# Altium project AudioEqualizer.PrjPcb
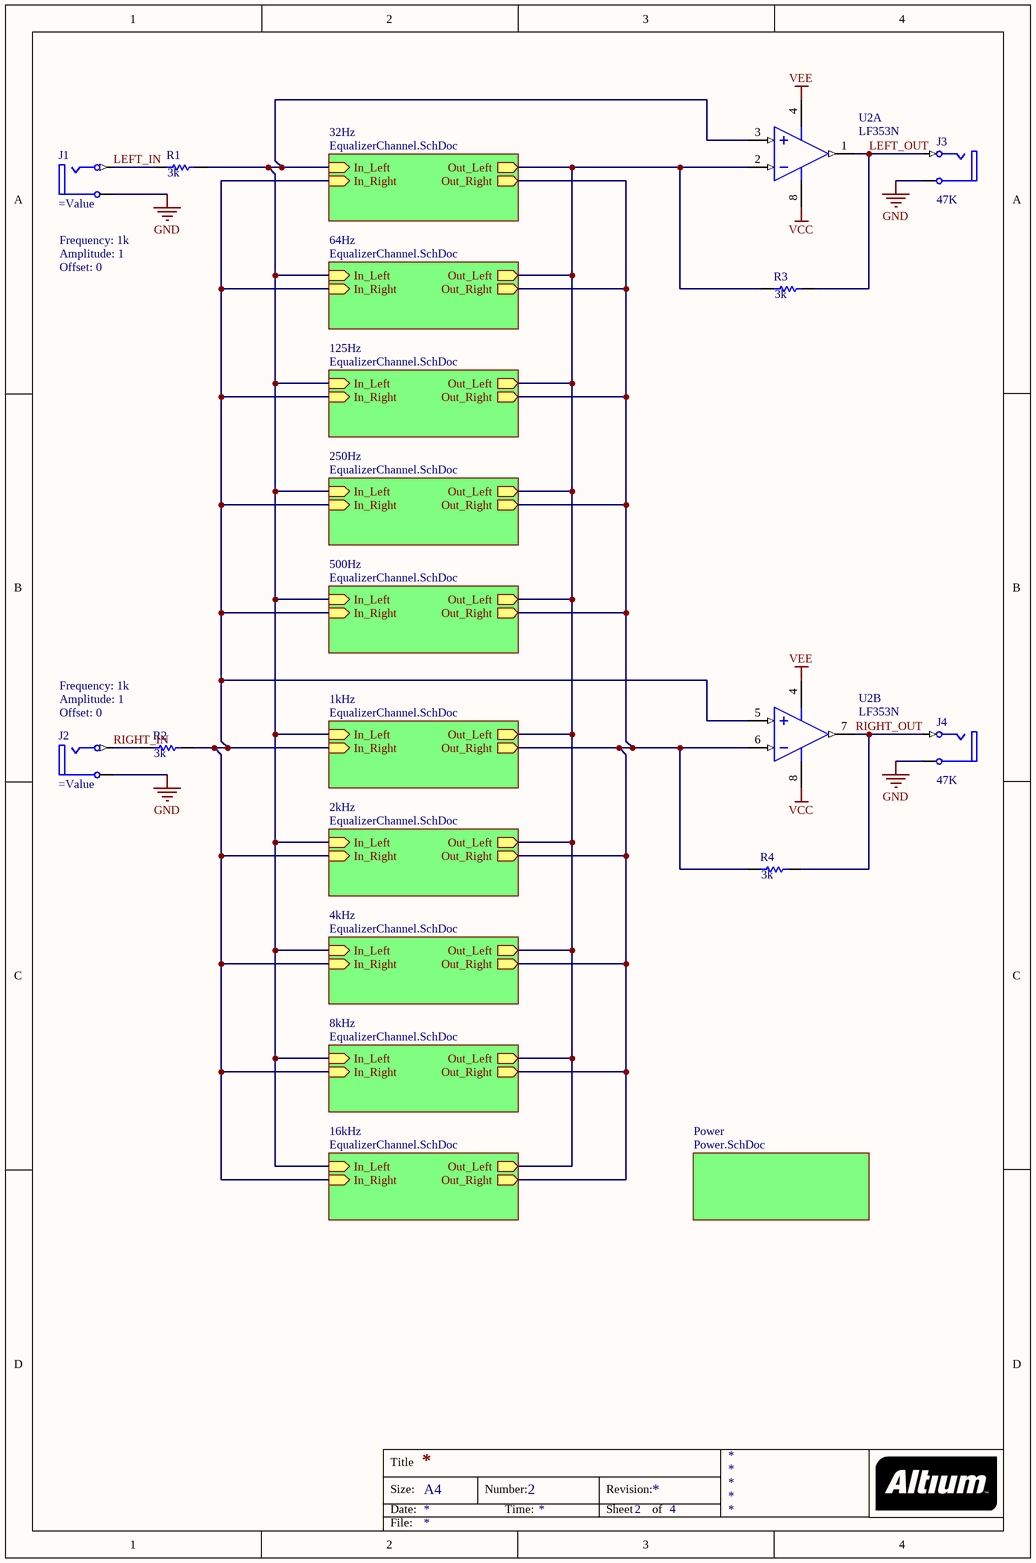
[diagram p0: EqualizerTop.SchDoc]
4 sheets, 139 parts. Net scope: hierarchical (ports join the sheet entries above them; power ports are global).
Sheets:
  EqualizerTop.SchDoc
    32Hz = EqualizerChannel.SchDoc
      Left = RCNetwork.SchDoc
      Right = RCNetwork.SchDoc
    64Hz = EqualizerChannel.SchDoc
      Left = RCNetwork.SchDoc
      Right = RCNetwork.SchDoc
    125Hz = EqualizerChannel.SchDoc
      Left = RCNetwork.SchDoc
      Right = RCNetwork.SchDoc
    250Hz = EqualizerChannel.SchDoc
      Left = RCNetwork.SchDoc
      Right = RCNetwork.SchDoc
    500Hz = EqualizerChannel.SchDoc
      Left = RCNetwork.SchDoc
      Right = RCNetwork.SchDoc
    1kHz = EqualizerChannel.SchDoc
      Left = RCNetwork.SchDoc
      Right = RCNetwork.SchDoc
    2kHz = EqualizerChannel.SchDoc
      Left = RCNetwork.SchDoc
      Right = RCNetwork.SchDoc
    4kHz = EqualizerChannel.SchDoc
      Left = RCNetwork.SchDoc
      Right = RCNetwork.SchDoc
    8kHz = EqualizerChannel.SchDoc
      Left = RCNetwork.SchDoc
      Right = RCNetwork.SchDoc
    16kHz = EqualizerChannel.SchDoc
      Left = RCNetwork.SchDoc
      Right = RCNetwork.SchDoc
    Power = Power.SchDoc

## Sheet EqualizerTop.SchDoc
size A4 portrait; DocumentNumber: 2; SheetNumber: 2; SheetTotal: 4

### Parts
J1  Offset: 0  Amplitude: 1  Frequency: 1k  [RCA/4.5-H2]
J2  Offset: 0  Amplitude: 1  Frequency: 1k  [RCA/4.5-H2]
J3  47K  [RCA/4.5-H2]
J4  47K  [RCA/4.5-H2]
R1  3k  [3216[1206]]
R2  3k  [3216[1206]]
R3  3k  [3216[1206]]
R4  3k  [3216[1206]]
U2  LF353N  [N08E]  (parts A,B of 2)

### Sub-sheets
1kHz = EqualizerChannel.SchDoc: In_Left (in), Out_Left (out), In_Right (in), Out_Right (out)  | C1_Value: 3.9nF; C2_Value: 0.22uF; R1_Value: 68k; R2_Value: 470; POT_SET: {SLIDER_1K}
2kHz = EqualizerChannel.SchDoc: In_Left (in), Out_Left (out), In_Right (in), Out_Right (out)  | C1_Value: 2nF; C2_Value: 0.1uF; R1_Value: 68k; R2_Value: 470; POT_SET: {SLIDER_2K}
4kHz = EqualizerChannel.SchDoc: In_Left (in), Out_Left (out), In_Right (in), Out_Right (out)  | C1_Value: 1.1nF; C2_Value: 0.056uF; R1_Value: 62k; R2_Value: 470; POT_SET: {SLIDER_4K}
8kHz = EqualizerChannel.SchDoc: In_Left (in), Out_Left (out), In_Right (in), Out_Right (out)  | C1_Value: 510pF; C2_Value: 0.022uF; R1_Value: 68k; R2_Value: 510; POT_SET: {SLIDER_8K}
16kHz = EqualizerChannel.SchDoc: In_Left (in), Out_Left (out), In_Right (in), Out_Right (out)  | C1_Value: 330pF; C2_Value: 0.012uF; R1_Value: 51k; R2_Value: 510; POT_SET: {SLIDER_16K}
32Hz = EqualizerChannel.SchDoc: In_Left (in), Out_Left (out), In_Right (in), Out_Right (out)  | C1_Value: 0.12uF; C2_Value: 4.7uF; R1_Value: 75k; R2_Value: 500; POT_SET: {SLIDER_32}
64Hz = EqualizerChannel.SchDoc: In_Left (in), Out_Left (out), In_Right (in), Out_Right (out)  | C1_Value: 0.056uF; C2_Value: 3.3uF; R1_Value: 68k; R2_Value: 510; POT_SET: {SLIDER_64}
125Hz = EqualizerChannel.SchDoc: In_Left (in), Out_Left (out), In_Right (in), Out_Right (out)  | C1_Value: 0.033uF; C2_Value: 1.5uF; R1_Value: 62k; R2_Value: 510; POT_SET: {SLIDER_125}
250Hz = EqualizerChannel.SchDoc: In_Left (in), Out_Left (out), In_Right (in), Out_Right (out)  | C1_Value: 0.015uF; C2_Value: 0.82uF; R1_Value: 68k; R2_Value: 470; POT_SET: {SLIDER_250}
500Hz = EqualizerChannel.SchDoc: In_Left (in), Out_Left (out), In_Right (in), Out_Right (out)  | C1_Value: 8.2nF; C2_Value: 0.39uF; R1_Value: 62k; R2_Value: 470; POT_SET: {SLIDER_500}
Power = Power.SchDoc: no entries

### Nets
GND: J1.1A(Ground) J2.1A(Ground) J3.1A(Ground) J4.1A(Ground)
VCC: U2.8(V+)
VEE: U2.4(V-)
LEFT_IN: J1.2B(Signal) R1.1
LEFT_OUT: J3.2B(Signal) R3.2 U2.1(OUTA)
RIGHT_IN: J2.2B(Signal) R2.1
RIGHT_OUT: J4.2B(Signal) R4.2 U2.7(OUTB)
NetR1_2: R1.2 U2.3(INA+) ; sheet 32Hz/In_Left, sheet 64Hz/In_Left, sheet 125Hz/In_Left, sheet 250Hz/In_Left, sheet 500Hz/In_Left, sheet 1kHz/In_Left, sheet 2kHz/In_Left, sheet 4kHz/In_Left, sheet 8kHz/In_Left, sheet 16kHz/In_Left
NetR2_2: R2.2 U2.5(INB+) ; sheet 32Hz/In_Right, sheet 64Hz/In_Right, sheet 125Hz/In_Right, sheet 250Hz/In_Right, sheet 500Hz/In_Right, sheet 1kHz/In_Right, sheet 2kHz/In_Right, sheet 4kHz/In_Right, sheet 8kHz/In_Right, sheet 16kHz/In_Right
NetR3_1: R3.1 U2.2(INA-) ; sheet 32Hz/Out_Left, sheet 64Hz/Out_Left, sheet 125Hz/Out_Left, sheet 250Hz/Out_Left, sheet 500Hz/Out_Left, sheet 1kHz/Out_Left, sheet 2kHz/Out_Left, sheet 4kHz/Out_Left, sheet 8kHz/Out_Left, sheet 16kHz/Out_Left
NetR4_1: R4.1 U2.6(INB-) ; sheet 32Hz/Out_Right, sheet 64Hz/Out_Right, sheet 125Hz/Out_Right, sheet 250Hz/Out_Right, sheet 500Hz/Out_Right, sheet 1kHz/Out_Right, sheet 2kHz/Out_Right, sheet 4kHz/Out_Right, sheet 8kHz/Out_Right, sheet 16kHz/Out_Right

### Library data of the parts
J1-J4 = RCA: RCA Phono Jack, Right Angle, Thru-Hole, Snap-In; PCB_Layout: Complies with manufacturer's recommendation.; DrillAndSlotSize: Corresponds to nominal value.
R1-R4 = Res1: Resistor
U2 = LF353N: Wide Bandwidth Dual JFET Input Operational Amplifier, 8-pin MDIP; Manufacturer: National Semiconductor; PackageTopMarking: NSUZXYTTE#*LF*353N; PowerWise: N; CompType: Amplifiers

## Sheet EqualizerChannel.SchDoc
size A4; DocumentNumber: 1; SheetNumber: 1; SheetTotal: 4
Used 10 times, as channels 32Hz, 64Hz, 125Hz, 250Hz, 500Hz, 1kHz, 2kHz, 4kHz, 8kHz, 16kHz. Parts and nets are listed once, with the designators drawn on the sheet.
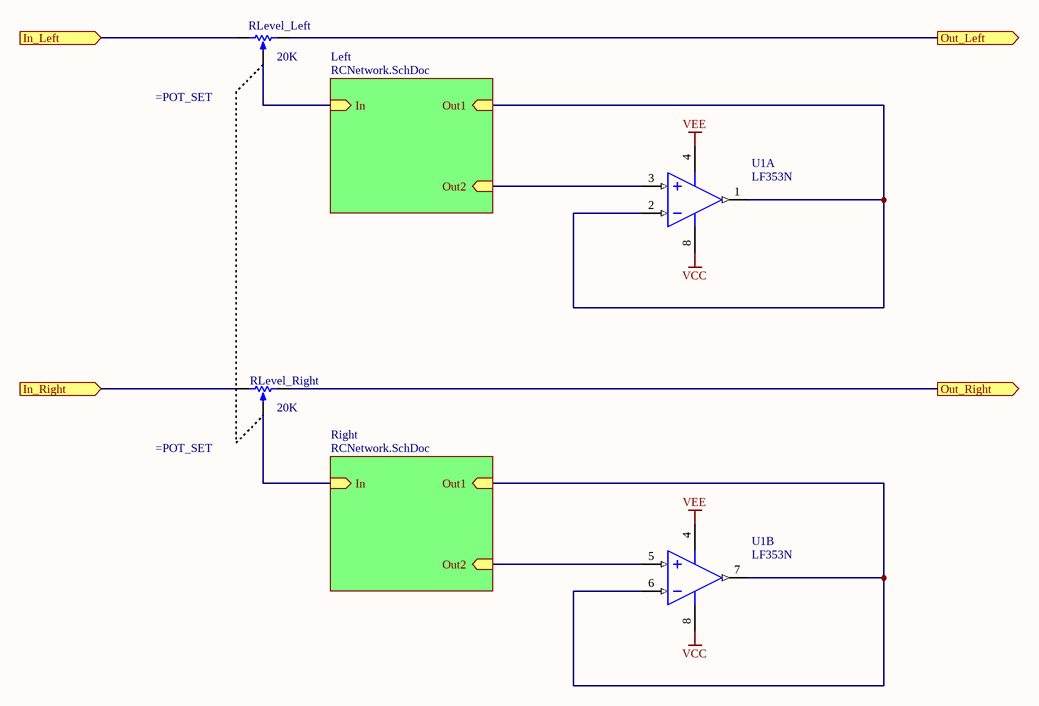
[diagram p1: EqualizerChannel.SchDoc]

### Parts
RLevel_Left  value 20K  [VR5]  (hidden comment: RPot)
RLevel_Right  value 20K  [VR5]  (hidden comment: RPot)
U1  LF353N  [N08E]  (parts A,B of 2)

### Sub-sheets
Left = RCNetwork.SchDoc: In (in), Out1 (in), Out2 (in)
Right = RCNetwork.SchDoc: In (in), Out1 (in), Out2 (in)

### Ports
In_Left (in), In_Right (in), Out_Left (out), Out_Right (out)

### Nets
VCC: U1.8(V+)
VEE: U1.4(V-)
In_Left: RLevel_Left.1(TOP) ; port In_Left
In_Right: RLevel_Right.1(TOP) ; port In_Right
Out_Left: RLevel_Left.2(BOT) ; port Out_Left
Out_Right: RLevel_Right.2(BOT) ; port Out_Right
NetRLevel_Left_3: RLevel_Left.3(TAP) ; sheet Left/In
NetRLevel_Right_3: RLevel_Right.3(TAP) ; sheet Right/In
NetU1_1: U1.1(OUTA) U1.2(INA-) ; sheet Left/Out1
NetU1_3: U1.3(INA+) ; sheet Left/Out2
NetU1_5: U1.5(INB+) ; sheet Right/Out2
NetU1_6: U1.6(INB-) U1.7(OUTB) ; sheet Right/Out1

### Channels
32Hz: designators end in _32Hz; ports In_Left=NetR1_2 In_Right=NetR2_2 Out_Left=NetR3_1 Out_Right=NetR4_1
64Hz: designators end in _64Hz; ports In_Left=NetR1_2 In_Right=NetR2_2 Out_Left=NetR3_1 Out_Right=NetR4_1
125Hz: designators end in _125Hz; ports In_Left=NetR1_2 In_Right=NetR2_2 Out_Left=NetR3_1 Out_Right=NetR4_1
250Hz: designators end in _250Hz; ports In_Left=NetR1_2 In_Right=NetR2_2 Out_Left=NetR3_1 Out_Right=NetR4_1
500Hz: designators end in _500Hz; ports In_Left=NetR1_2 In_Right=NetR2_2 Out_Left=NetR3_1 Out_Right=NetR4_1
1kHz: designators end in _1kHz; ports In_Left=NetR1_2 In_Right=NetR2_2 Out_Left=NetR3_1 Out_Right=NetR4_1
2kHz: designators end in _2kHz; ports In_Left=NetR1_2 In_Right=NetR2_2 Out_Left=NetR3_1 Out_Right=NetR4_1
4kHz: designators end in _4kHz; ports In_Left=NetR1_2 In_Right=NetR2_2 Out_Left=NetR3_1 Out_Right=NetR4_1
8kHz: designators end in _8kHz; ports In_Left=NetR1_2 In_Right=NetR2_2 Out_Left=NetR3_1 Out_Right=NetR4_1
16kHz: designators end in _16kHz; ports In_Left=NetR1_2 In_Right=NetR2_2 Out_Left=NetR3_1 Out_Right=NetR4_1

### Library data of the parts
RLevel_Left RLevel_Right = RPot: Potentiometer; Sim Note: Enter the Resistance value and the set point into parameter fields.
U1 = LF353N: as U2 on sheet EqualizerTop

## Sheet RCNetwork.SchDoc
size A4; DocumentNumber: 3; SheetNumber: 3; SheetTotal: 4
Used 20 times, as channels 32Hz/Left, 32Hz/Right, 64Hz/Left, 64Hz/Right, 125Hz/Left, 125Hz/Right, 250Hz/Left, 250Hz/Right, 500Hz/Left, 500Hz/Right, 1kHz/Left, 1kHz/Right, 2kHz/Left, 2kHz/Right, 4kHz/Left, 4kHz/Right, 8kHz/Left, 8kHz/Right, 16kHz/Left, 16kHz/Right. Parts and nets are listed once, with the designators drawn on the sheet.
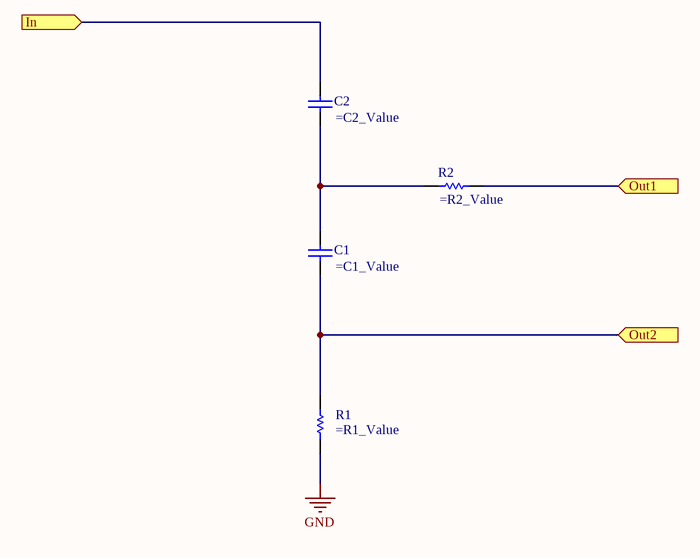
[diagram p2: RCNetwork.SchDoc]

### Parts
C1  (no value)  [C1206]
C2  (no value)  [C1206]
R1  (no value)  [3216[1206]]
R2  (no value)  [3216[1206]]

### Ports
In (in), Out1 (in), Out2 (in)

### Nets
GND: R1.1
In: C2.1 ; port In
Out1: R2.1 ; port Out1
Out2: C1.2 R1.2 ; port Out2
NetC1_1: C1.1 C2.2 R2.2

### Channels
32Hz/Left: designators end in _32Hz_Left; ports In=NetC2_32Hz_Left_1 Out1=NetR2_32Hz_Left_1 Out2=NetC1_32Hz_Left_2
32Hz/Right: designators end in _32Hz_Right; ports In=NetC2_32Hz_Right_1 Out1=NetR2_32Hz_Right_1 Out2=NetC1_32Hz_Right_2
64Hz/Left: designators end in _64Hz_Left; ports In=NetC2_64Hz_Left_1 Out1=NetR2_64Hz_Left_1 Out2=NetC1_64Hz_Left_2
64Hz/Right: designators end in _64Hz_Right; ports In=NetC2_64Hz_Right_1 Out1=NetR2_64Hz_Right_1 Out2=NetC1_64Hz_Right_2
125Hz/Left: designators end in _125Hz_Left; ports In=NetC2_125Hz_Left_1 Out1=NetR2_125Hz_Left_1 Out2=NetC1_125Hz_Left_2
125Hz/Right: designators end in _125Hz_Right; ports In=NetC2_125Hz_Right_1 Out1=NetR2_125Hz_Right_1 Out2=NetC1_125Hz_Right_2
250Hz/Left: designators end in _250Hz_Left; ports In=NetC2_250Hz_Left_1 Out1=NetR2_250Hz_Left_1 Out2=NetC1_250Hz_Left_2
250Hz/Right: designators end in _250Hz_Right; ports In=NetC2_250Hz_Right_1 Out1=NetR2_250Hz_Right_1 Out2=NetC1_250Hz_Right_2
500Hz/Left: designators end in _500Hz_Left; ports In=NetC2_500Hz_Left_1 Out1=NetR2_500Hz_Left_1 Out2=NetC1_500Hz_Left_2
500Hz/Right: designators end in _500Hz_Right; ports In=NetC2_500Hz_Right_1 Out1=NetR2_500Hz_Right_1 Out2=NetC1_500Hz_Right_2
1kHz/Left: designators end in _1kHz_Left; ports In=NetC2_1kHz_Left_1 Out1=NetR2_1kHz_Left_1 Out2=NetC1_1kHz_Left_2
1kHz/Right: designators end in _1kHz_Right; ports In=NetC2_1kHz_Right_1 Out1=NetR2_1kHz_Right_1 Out2=NetC1_1kHz_Right_2
2kHz/Left: designators end in _2kHz_Left; ports In=NetC2_2kHz_Left_1 Out1=NetR2_2kHz_Left_1 Out2=NetC1_2kHz_Left_2
2kHz/Right: designators end in _2kHz_Right; ports In=NetC2_2kHz_Right_1 Out1=NetR2_2kHz_Right_1 Out2=NetC1_2kHz_Right_2
4kHz/Left: designators end in _4kHz_Left; ports In=NetC2_4kHz_Left_1 Out1=NetR2_4kHz_Left_1 Out2=NetC1_4kHz_Left_2
4kHz/Right: designators end in _4kHz_Right; ports In=NetC2_4kHz_Right_1 Out1=NetR2_4kHz_Right_1 Out2=NetC1_4kHz_Right_2
8kHz/Left: designators end in _8kHz_Left; ports In=NetC2_8kHz_Left_1 Out1=NetR2_8kHz_Left_1 Out2=NetC1_8kHz_Left_2
8kHz/Right: designators end in _8kHz_Right; ports In=NetC2_8kHz_Right_1 Out1=NetR2_8kHz_Right_1 Out2=NetC1_8kHz_Right_2
16kHz/Left: designators end in _16kHz_Left; ports In=NetC2_16kHz_Left_1 Out1=NetR2_16kHz_Left_1 Out2=NetC1_16kHz_Left_2
16kHz/Right: designators end in _16kHz_Right; ports In=NetC2_16kHz_Right_1 Out1=NetR2_16kHz_Right_1 Out2=NetC1_16kHz_Right_2

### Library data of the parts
C1 C2 = Cap: Capacitor
R1 R2 = Res1: Resistor

## Sheet Power.SchDoc
size A4; DocumentNumber: 4; SheetNumber: 4; SheetTotal: 4
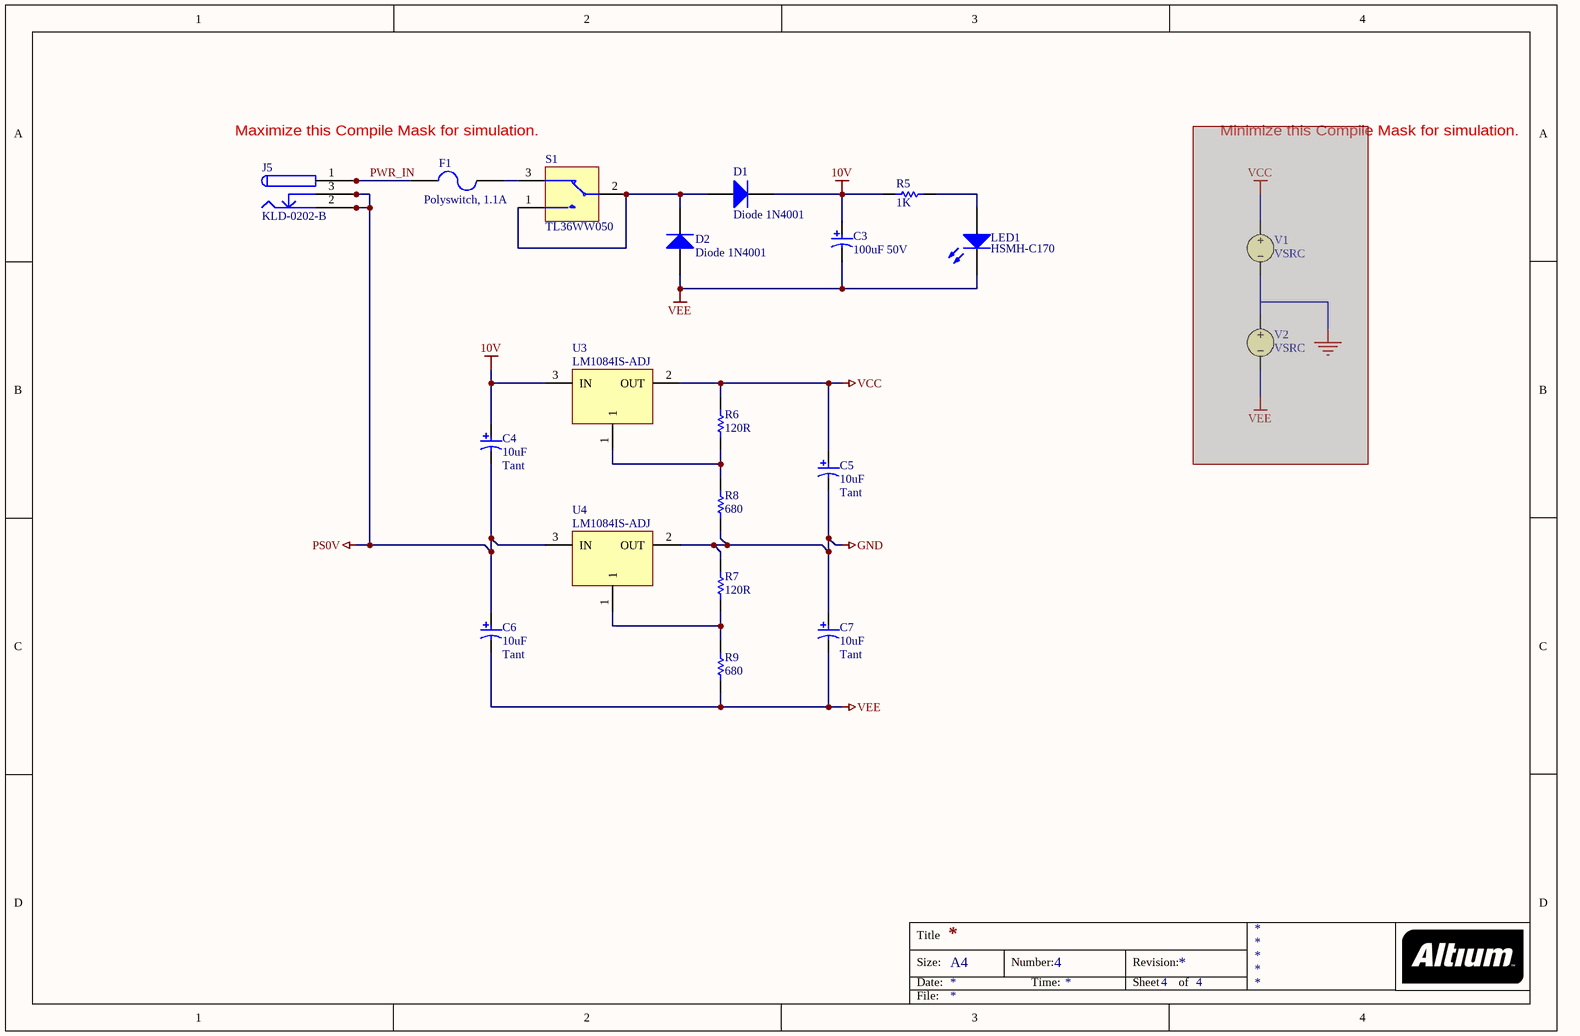
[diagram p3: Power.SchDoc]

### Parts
C3  100uF 50V  [MCCT-B]
C4  10uF  Capacitor Type: Tant  [MCCT-B]
C5  10uF  Capacitor Type: Tant  [MCCT-B]
C6  10uF  Capacitor Type: Tant  [MCCT-B]
C7  10uF  Capacitor Type: Tant  [MCCT-B]
D1  Diode 1N4001  [DO-41]
D2  Diode 1N4001  [DO-41]
F1  Polyswitch, 1.1A  [PIN-W2/E2.8]
J5  KLD-0202-B  [KLD-0202]
LED1  HSMH-C170  [SMD _LED]
R5  1K  [3216[1206]]
R6  120R  [3216[1206]]
R7  120R  [3216[1206]]
R8  680  [3216[1206]]
R9  680  [3216[1206]]
S1  TL36WW050  [B3FS_SWITCH]
U3  LM1084IS-ADJ  [TO-263]
U4  LM1084IS-ADJ  [TO-263]
V1  VSRC  (masked out: inside a compile mask, not in the netlist)
V2  VSRC  (masked out: inside a compile mask, not in the netlist)

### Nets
10V: C3.1 C4.1 D1.2(K) R5.2 U3.3(IN)
GND: C5.2 C7.1 R7.1 R8.2 U4.2(OUT)
PS0V: C4.2 C6.1 J5.2 J5.2A J5.2B J5.3 J5.3A J5.3B U4.3(IN)
VCC: C5.1 R6.1 U3.2(OUT)
VEE: C3.2 C6.2 C7.2 D2.1(A) LED1.2(K) R9.2
PWR_IN: F1.1 J5.1 J5.1A J5.1B
NetD1_1: D1.1(A) D2.2(K) S1.1 S1.2
NetF1_2: F1.2 S1.3
NetLED1_1: LED1.1(A) R5.1
NetR6_2: R6.2 R8.1 U3.1
NetR7_2: R7.2 R9.1 U4.1

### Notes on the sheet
- Maximize this Compile Mask for simulation.
- Minimize this Compile Mask for simulation.

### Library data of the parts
C3 = CAP_POLAR: Polar Capacitor
C4-C7 = CAP_POLAR: Polar Capacitor; AEMS Code: 2100110
D1 D2 = Diode 1N4001: 1 Amp General Purpose Rectifier
F1 = Fuse 2: Polyswitch 1.1A, Raychem RUE110
J5 = KLD-0202-B: Low Voltage Power Supply Connector; Manufacturer: Kycon; AEMS Code: 3510211
LED1 = HSMX-C670: Typical RED GaAs SMD LED Agilent make; AEMS Code: 2610081
R5 = RES: Resistor; AEMS Code: 1200430
R6-R9 = Res1: Resistor
S1 = PCB_MOUNT_SWITCH: SPDT Subminiature Toggle Switch
U3 U4 = LM1084IS-ADJ: 5A Low Dropout Possitive Regulators
V1 = VSRC: Voltage Source; Note: PCB Footprint - Not required; Value: 8V
V2 = VSRC: Voltage Source; Note: PCB Footprint - Not required; Value: 8

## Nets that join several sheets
GND: EqualizerTop (J1.1A J2.1A J3.1A J4.1A), 32Hz/Left (R1_32Hz_Left.1), 32Hz/Right (R1_32Hz_Right.1), 64Hz/Left (R1_64Hz_Left.1), 64Hz/Right (R1_64Hz_Right.1), 125Hz/Left (R1_125Hz_Left.1), 125Hz/Right (R1_125Hz_Right.1), 250Hz/Left (R1_250Hz_Left.1), 250Hz/Right (R1_250Hz_Right.1), 500Hz/Left (R1_500Hz_Left.1), 500Hz/Right (R1_500Hz_Right.1), 1kHz/Left (R1_1kHz_Left.1), 1kHz/Right (R1_1kHz_Right.1), 2kHz/Left (R1_2kHz_Left.1), 2kHz/Right (R1_2kHz_Right.1), 4kHz/Left (R1_4kHz_Left.1), 4kHz/Right (R1_4kHz_Right.1), 8kHz/Left (R1_8kHz_Left.1), 8kHz/Right (R1_8kHz_Right.1), 16kHz/Left (R1_16kHz_Left.1), 16kHz/Right (R1_16kHz_Right.1), Power (5 pins)
VCC: EqualizerTop (U2.8), 32Hz (U1_32Hz.8), 64Hz (U1_64Hz.8), 125Hz (U1_125Hz.8), 250Hz (U1_250Hz.8), 500Hz (U1_500Hz.8), 1kHz (U1_1kHz.8), 2kHz (U1_2kHz.8), 4kHz (U1_4kHz.8), 8kHz (U1_8kHz.8), 16kHz (U1_16kHz.8), Power (C5.1 R6.1 U3.2)
VEE: EqualizerTop (U2.4), 32Hz (U1_32Hz.4), 64Hz (U1_64Hz.4), 125Hz (U1_125Hz.4), 250Hz (U1_250Hz.4), 500Hz (U1_500Hz.4), 1kHz (U1_1kHz.4), 2kHz (U1_2kHz.4), 4kHz (U1_4kHz.4), 8kHz (U1_8kHz.4), 16kHz (U1_16kHz.4), Power (6 pins)
NetC1_1kHz_Left_2: 1kHz (U1_1kHz.3), 1kHz/Left (C1_1kHz_Left.2 R1_1kHz_Left.2)
NetC1_1kHz_Right_2: 1kHz (U1_1kHz.5), 1kHz/Right (C1_1kHz_Right.2 R1_1kHz_Right.2)
NetC1_2kHz_Left_2: 2kHz (U1_2kHz.3), 2kHz/Left (C1_2kHz_Left.2 R1_2kHz_Left.2)
NetC1_2kHz_Right_2: 2kHz (U1_2kHz.5), 2kHz/Right (C1_2kHz_Right.2 R1_2kHz_Right.2)
NetC1_4kHz_Left_2: 4kHz (U1_4kHz.3), 4kHz/Left (C1_4kHz_Left.2 R1_4kHz_Left.2)
NetC1_4kHz_Right_2: 4kHz (U1_4kHz.5), 4kHz/Right (C1_4kHz_Right.2 R1_4kHz_Right.2)
NetC1_8kHz_Left_2: 8kHz (U1_8kHz.3), 8kHz/Left (C1_8kHz_Left.2 R1_8kHz_Left.2)
NetC1_8kHz_Right_2: 8kHz (U1_8kHz.5), 8kHz/Right (C1_8kHz_Right.2 R1_8kHz_Right.2)
NetC1_16kHz_Left_2: 16kHz (U1_16kHz.3), 16kHz/Left (C1_16kHz_Left.2 R1_16kHz_Left.2)
NetC1_16kHz_Right_2: 16kHz (U1_16kHz.5), 16kHz/Right (C1_16kHz_Right.2 R1_16kHz_Right.2)
NetC1_32Hz_Left_2: 32Hz (U1_32Hz.3), 32Hz/Left (C1_32Hz_Left.2 R1_32Hz_Left.2)
NetC1_32Hz_Right_2: 32Hz (U1_32Hz.5), 32Hz/Right (C1_32Hz_Right.2 R1_32Hz_Right.2)
NetC1_64Hz_Left_2: 64Hz (U1_64Hz.3), 64Hz/Left (C1_64Hz_Left.2 R1_64Hz_Left.2)
NetC1_64Hz_Right_2: 64Hz (U1_64Hz.5), 64Hz/Right (C1_64Hz_Right.2 R1_64Hz_Right.2)
NetC1_125Hz_Left_2: 125Hz (U1_125Hz.3), 125Hz/Left (C1_125Hz_Left.2 R1_125Hz_Left.2)
NetC1_125Hz_Right_2: 125Hz (U1_125Hz.5), 125Hz/Right (C1_125Hz_Right.2 R1_125Hz_Right.2)
NetC1_250Hz_Left_2: 250Hz (U1_250Hz.3), 250Hz/Left (C1_250Hz_Left.2 R1_250Hz_Left.2)
NetC1_250Hz_Right_2: 250Hz (U1_250Hz.5), 250Hz/Right (C1_250Hz_Right.2 R1_250Hz_Right.2)
NetC1_500Hz_Left_2: 500Hz (U1_500Hz.3), 500Hz/Left (C1_500Hz_Left.2 R1_500Hz_Left.2)
NetC1_500Hz_Right_2: 500Hz (U1_500Hz.5), 500Hz/Right (C1_500Hz_Right.2 R1_500Hz_Right.2)
NetC2_1kHz_Left_1: 1kHz (RLevel_Left_1kHz.3), 1kHz/Left (C2_1kHz_Left.1)
NetC2_1kHz_Right_1: 1kHz (RLevel_Right_1kHz.3), 1kHz/Right (C2_1kHz_Right.1)
NetC2_2kHz_Left_1: 2kHz (RLevel_Left_2kHz.3), 2kHz/Left (C2_2kHz_Left.1)
NetC2_2kHz_Right_1: 2kHz (RLevel_Right_2kHz.3), 2kHz/Right (C2_2kHz_Right.1)
NetC2_4kHz_Left_1: 4kHz (RLevel_Left_4kHz.3), 4kHz/Left (C2_4kHz_Left.1)
NetC2_4kHz_Right_1: 4kHz (RLevel_Right_4kHz.3), 4kHz/Right (C2_4kHz_Right.1)
NetC2_8kHz_Left_1: 8kHz (RLevel_Left_8kHz.3), 8kHz/Left (C2_8kHz_Left.1)
NetC2_8kHz_Right_1: 8kHz (RLevel_Right_8kHz.3), 8kHz/Right (C2_8kHz_Right.1)
NetC2_16kHz_Left_1: 16kHz (RLevel_Left_16kHz.3), 16kHz/Left (C2_16kHz_Left.1)
NetC2_16kHz_Right_1: 16kHz (RLevel_Right_16kHz.3), 16kHz/Right (C2_16kHz_Right.1)
NetC2_32Hz_Left_1: 32Hz (RLevel_Left_32Hz.3), 32Hz/Left (C2_32Hz_Left.1)
NetC2_32Hz_Right_1: 32Hz (RLevel_Right_32Hz.3), 32Hz/Right (C2_32Hz_Right.1)
NetC2_64Hz_Left_1: 64Hz (RLevel_Left_64Hz.3), 64Hz/Left (C2_64Hz_Left.1)
NetC2_64Hz_Right_1: 64Hz (RLevel_Right_64Hz.3), 64Hz/Right (C2_64Hz_Right.1)
NetC2_125Hz_Left_1: 125Hz (RLevel_Left_125Hz.3), 125Hz/Left (C2_125Hz_Left.1)
NetC2_125Hz_Right_1: 125Hz (RLevel_Right_125Hz.3), 125Hz/Right (C2_125Hz_Right.1)
NetC2_250Hz_Left_1: 250Hz (RLevel_Left_250Hz.3), 250Hz/Left (C2_250Hz_Left.1)
NetC2_250Hz_Right_1: 250Hz (RLevel_Right_250Hz.3), 250Hz/Right (C2_250Hz_Right.1)
NetC2_500Hz_Left_1: 500Hz (RLevel_Left_500Hz.3), 500Hz/Left (C2_500Hz_Left.1)
NetC2_500Hz_Right_1: 500Hz (RLevel_Right_500Hz.3), 500Hz/Right (C2_500Hz_Right.1)
NetR1_2: EqualizerTop (R1.2 U2.3), 32Hz (RLevel_Left_32Hz.1), 64Hz (RLevel_Left_64Hz.1), 125Hz (RLevel_Left_125Hz.1), 250Hz (RLevel_Left_250Hz.1), 500Hz (RLevel_Left_500Hz.1), 1kHz (RLevel_Left_1kHz.1), 2kHz (RLevel_Left_2kHz.1), 4kHz (RLevel_Left_4kHz.1), 8kHz (RLevel_Left_8kHz.1), 16kHz (RLevel_Left_16kHz.1)
NetR2_1kHz_Left_1: 1kHz (U1_1kHz.1 U1_1kHz.2), 1kHz/Left (R2_1kHz_Left.1)
NetR2_1kHz_Right_1: 1kHz (U1_1kHz.6 U1_1kHz.7), 1kHz/Right (R2_1kHz_Right.1)
NetR2_2: EqualizerTop (R2.2 U2.5), 32Hz (RLevel_Right_32Hz.1), 64Hz (RLevel_Right_64Hz.1), 125Hz (RLevel_Right_125Hz.1), 250Hz (RLevel_Right_250Hz.1), 500Hz (RLevel_Right_500Hz.1), 1kHz (RLevel_Right_1kHz.1), 2kHz (RLevel_Right_2kHz.1), 4kHz (RLevel_Right_4kHz.1), 8kHz (RLevel_Right_8kHz.1), 16kHz (RLevel_Right_16kHz.1)
NetR2_2kHz_Left_1: 2kHz (U1_2kHz.1 U1_2kHz.2), 2kHz/Left (R2_2kHz_Left.1)
NetR2_2kHz_Right_1: 2kHz (U1_2kHz.6 U1_2kHz.7), 2kHz/Right (R2_2kHz_Right.1)
NetR2_4kHz_Left_1: 4kHz (U1_4kHz.1 U1_4kHz.2), 4kHz/Left (R2_4kHz_Left.1)
NetR2_4kHz_Right_1: 4kHz (U1_4kHz.6 U1_4kHz.7), 4kHz/Right (R2_4kHz_Right.1)
NetR2_8kHz_Left_1: 8kHz (U1_8kHz.1 U1_8kHz.2), 8kHz/Left (R2_8kHz_Left.1)
NetR2_8kHz_Right_1: 8kHz (U1_8kHz.6 U1_8kHz.7), 8kHz/Right (R2_8kHz_Right.1)
NetR2_16kHz_Left_1: 16kHz (U1_16kHz.1 U1_16kHz.2), 16kHz/Left (R2_16kHz_Left.1)
NetR2_16kHz_Right_1: 16kHz (U1_16kHz.6 U1_16kHz.7), 16kHz/Right (R2_16kHz_Right.1)
NetR2_32Hz_Left_1: 32Hz (U1_32Hz.1 U1_32Hz.2), 32Hz/Left (R2_32Hz_Left.1)
NetR2_32Hz_Right_1: 32Hz (U1_32Hz.6 U1_32Hz.7), 32Hz/Right (R2_32Hz_Right.1)
NetR2_64Hz_Left_1: 64Hz (U1_64Hz.1 U1_64Hz.2), 64Hz/Left (R2_64Hz_Left.1)
NetR2_64Hz_Right_1: 64Hz (U1_64Hz.6 U1_64Hz.7), 64Hz/Right (R2_64Hz_Right.1)
NetR2_125Hz_Left_1: 125Hz (U1_125Hz.1 U1_125Hz.2), 125Hz/Left (R2_125Hz_Left.1)
NetR2_125Hz_Right_1: 125Hz (U1_125Hz.6 U1_125Hz.7), 125Hz/Right (R2_125Hz_Right.1)
NetR2_250Hz_Left_1: 250Hz (U1_250Hz.1 U1_250Hz.2), 250Hz/Left (R2_250Hz_Left.1)
NetR2_250Hz_Right_1: 250Hz (U1_250Hz.6 U1_250Hz.7), 250Hz/Right (R2_250Hz_Right.1)
NetR2_500Hz_Left_1: 500Hz (U1_500Hz.1 U1_500Hz.2), 500Hz/Left (R2_500Hz_Left.1)
NetR2_500Hz_Right_1: 500Hz (U1_500Hz.6 U1_500Hz.7), 500Hz/Right (R2_500Hz_Right.1)
NetR3_1: EqualizerTop (R3.1 U2.2), 32Hz (RLevel_Left_32Hz.2), 64Hz (RLevel_Left_64Hz.2), 125Hz (RLevel_Left_125Hz.2), 250Hz (RLevel_Left_250Hz.2), 500Hz (RLevel_Left_500Hz.2), 1kHz (RLevel_Left_1kHz.2), 2kHz (RLevel_Left_2kHz.2), 4kHz (RLevel_Left_4kHz.2), 8kHz (RLevel_Left_8kHz.2), 16kHz (RLevel_Left_16kHz.2)
NetR4_1: EqualizerTop (R4.1 U2.6), 32Hz (RLevel_Right_32Hz.2), 64Hz (RLevel_Right_64Hz.2), 125Hz (RLevel_Right_125Hz.2), 250Hz (RLevel_Right_250Hz.2), 500Hz (RLevel_Right_500Hz.2), 1kHz (RLevel_Right_1kHz.2), 2kHz (RLevel_Right_2kHz.2), 4kHz (RLevel_Right_4kHz.2), 8kHz (RLevel_Right_8kHz.2), 16kHz (RLevel_Right_16kHz.2)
